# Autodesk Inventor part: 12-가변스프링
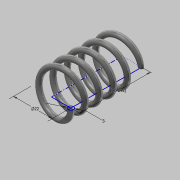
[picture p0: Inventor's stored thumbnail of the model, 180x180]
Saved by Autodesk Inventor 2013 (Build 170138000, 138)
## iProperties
Created: 2015-02
Part Number: 12-가변스프링
Material: 강철, 탄소
Document SubType Name: Modeling
Designer: Administrator
Density: 7.87 g/cm^3
Mass: 18.9202 g
Surface Area: 32.5617 cm^2
Volume: 2.40409 cm^3
Author: Administrator
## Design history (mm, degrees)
sketch "스케치1"
  geometry: L1 (0, 0)-(11, 0); L2 (11, 0)-(11, 40.245); L3 (11, 40.245)-(0, 40.245); L4 (0, 40.245)-(0, 0); C1 r 1.5 at (11, 0)
  constraints: 8 end point, 2 parallel, 1 centre point, 1 coincident, 1 horizontal, 1 perpendicular
  dimensions: "d0" = 40.2455 distance of L1.end L2.end (derived); "d2" = 22 diameter of L2 L4; "d3" = 3 diameter of C1
feature "코일1" sketch "스케치1" pitch "d4" = 10; turns "d6" = 5; dims "d5" = 40.2455 (= d0), "d7" = 0, angle "d8" = 90 deg, angle "d9" = 90 deg, "d10" = 0, "d11" = 0
node "작업 평면1"
sketch "스케치2"
  geometry: L1 (-12.5, 0)-(-9.5, 0) reference; L2 (-12.5, 0)-(-9.5, 0) reference; 1 further point
  constraints: 2 horizontal alignment
extrude "돌출1" cut sketch "스케치2" distance "d13" = 10; taper "d14" = 0 deg
node "작업 평면2"
sketch "스케치3"
  geometry: L1 (-9.5, 0)-(-12.5, 0) reference; 1 further point
  constraints: 1 horizontal alignment
extrude "돌출2" cut sketch "스케치3" distance "d16" = 10; taper "d17" = 0 deg
node "솔리드1"
node "절단 모서리 투영1"
node "절단 모서리 투영2"
node "절단 모서리 투영3"
other parameters: "d12" = 0, "d15" = 40.2455 (= d0)
